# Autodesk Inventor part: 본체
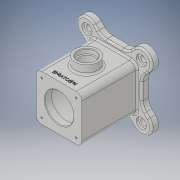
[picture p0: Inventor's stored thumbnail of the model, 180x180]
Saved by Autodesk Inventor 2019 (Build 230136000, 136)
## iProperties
Created: 2021-01
Part Number: 본체
Material: 일반
Document SubType Name: Modeling
Designer: 3DPRO16
Density: 1 g/cm^3
Appearance: 기본값
Author: 3DPRO16
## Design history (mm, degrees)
sketch "스케치1"
  geometry: L1 (-40, -40)-(40, -40); L2 (40, -40)-(40, 40); L3 (40, 40)-(-40, 40); L4 (-40, 40)-(-40, -40); L5 (-40, -40)-(40, 40); L6 (40, -40)-(-40, 40); 1 further point
  constraints: 12 end point, 2 midpoint, 2 parallel, 1 horizontal, 1 perpendicular
  dimensions: "d0" = 80 distance of L3.end L2.end; "d1" = 80 distance of L2.end L1.end
extrude "돌출1" new body sketch "스케치1" stored distance "d2" = 96; taper "d3" = 0 deg
sketch "스케치3"
  geometry: C1 r 25 at (0, 0); 1 further point
  constraints: 1 centre point, 1 coincident
  dimensions: "d7" = 50 diameter of C1
extrude "돌출3" cut sketch "스케치3" distance "d8" = 12; taper "d9" = 0 deg
sketch "스케치4"
  geometry: L1 (-48, -48)-(48, -48); L2 (48, -48)-(48, 48); L3 (48, 48)-(-48, 48); L4 (-48, 48)-(-48, -48); L5 (-48, -48)-(48, 48); L6 (48, -48)-(-48, 48); 1 further point
  constraints: 12 end point, 2 midpoint, 2 parallel, 1 horizontal, 1 perpendicular
  dimensions: "d10" = 96 distance of L3.end L2.end; "d11" = 96 distance of L2.end L1.end
extrude "돌출4" join sketch "스케치4" distance "d12" = 12; taper "d13" = 0 deg
sketch "스케치5" dims "d36" = 134
  geometry: L1 (-48, 48)-(-48, -48) reference; L2 (48, 48)-(-48, 48) reference; L3 (-48, 48)-(-48, -48) reference; L4 (0, 0)-(-48, 48); L5 (-60.104, 34.648)-(-48, 22.544); L6 (-34.648, 60.104)-(-22.544, 48); A1 r 18 centre (-47.376, 47.376) between (-60.104, 34.648) and (-34.648, 60.104); 3 further points
  constraints: 6 end point, 5 point on line, 2 coincident, 2 parallel, 2 point on circle, 2 tangent, 1 centre point, 3 other
  dimensions: "d38" = 36 diameter of A1
sketch "스케치7"
  geometry: C1 r 35 at (0, 0); 1 further point
  constraints: 1 centre point, 1 coincident
  dimensions: "d30" = 70 diameter of C1
extrude "돌출6" cut sketch "스케치7" distance "d31" = 84; taper "d32" = 0 deg
sketch "스케치8"
  geometry: C1 r 25 at (0, 0); 1 further point
  constraints: 1 centre point, 1 coincident
  dimensions: "d33" = 50 diameter of C1
extrude "돌출7" cut sketch "스케치8" distance "d34" = 12; taper "d35" = 0 deg
extrude "돌출8" join sketch "스케치5" distance "d39" = 12; taper "d40" = 0 deg
sketch "스케치9"
  geometry: A1 r 18 centre (47.376, 47.376) between (60.104, 34.648) and (34.648, 60.104) reference; 2 further points
  constraints: 1 coincident
hole "구멍2" sketch "스케치9" at (47.376, 47.376) diameter "d41" = 10; stored, may be unused: countersink angle "d45" = 90 deg, drill point angle "d47" = 118 deg; dims "d42" = 6, "d43" = 18, "d44" = 4, "d46" = 26.75
sketch "스케치10"
  geometry: C1 r 20 at (40, 48); 1 further point
  constraints: 1 centre point, 1 coincident
  dimensions: "d51" = 40 diameter of C1
extrude "돌출9" join sketch "스케치10" distance "d52" = 15; taper "d53" = 0 deg
sketch "스케치11"
  geometry: C1 r 20 at (0, 0) reference; 2 further points
  constraints: 1 coincident
hole "구멍3" sketch "스케치11" at (0, 0) diameter "d54" = 25; stored, may be unused: countersink angle "d58" = 90 deg, drill point angle "d60" = 118 deg; dims "d55" = 6, "d56" = 30, "d57" = 8, "d59" = 45.25
sketch "스케치12"
  geometry: L1 (80, 0)-(0, 0) reference; 2 further points
  constraints: 1 vertical alignment, 1 other
  dimensions: "d61" = 10 distance from line of L1 point (40, 10)
feature "엠보싱1" sketch "스케치12" dims "d0" = 80, "d1" = 80, "d62" = 0.5, "d63" = 0
fillet "모깎기1" dims "d64" = 10
sketch "스케치13"
  geometry: A1 r 10 centre (-30, 30) between (-30, 40) and (-40, 30) reference; 2 further points
  constraints: 1 coincident
hole "구멍4" sketch "스케치13" at (-30, 30) diameter "d65" = 3.242; stored, may be unused: countersink angle "d69" = 90 deg, drill point angle "d71" = 118 deg; dims "d66" = 8, "d67" = 30, "d68" = 8, "d70" = 10
sketch "스케치14"
  geometry: L1 (-30, -30)-(30, -30); L2 (30, -30)-(30, 30); L3 (30, 30)-(-30, 30); L4 (-30, 30)-(-30, -30); L5 (-30, -30)-(30, 30); L6 (30, -30)-(-30, 30); C1 r 1.621 at (30, 30) reference; C2 r 1.621 at (30, -30) reference; 5 further points
  constraints: 12 end point, 4 coincident, 2 midpoint, 2 parallel, 1 horizontal, 1 perpendicular
  dimensions: "d78" = 60 distance of L3.end L2.end (derived); "d79" = 60 distance of L2.end L1.end (derived)
hole "구멍5" sketch "스케치14" at (-30, 30), (30, 30), (30, -30), (-30, -30) diameter "d80" = 3.242; stored, may be unused: countersink angle "d84" = 90 deg, drill point angle "d86" = 118 deg; dims "d81" = 8, "d82" = 30, "d83" = 8, "d85" = 10
fillet "모깎기2" dims "d87" = 20
fillet "모깎기3" dims "d88" = 3
chamfer "모따기1" distance "d89" = 1; stored, may be unused: second distance "d90" = 2, angle "d91" = 45 deg
fillet "모깎기4" dims "d92" = 3
node "솔리드1"
pattern_circular "원형 패턴3" dims angle "d49" = 360 deg
pattern_linear "직사각형 패턴1" dims "d74" = 60, "d77" = 60
